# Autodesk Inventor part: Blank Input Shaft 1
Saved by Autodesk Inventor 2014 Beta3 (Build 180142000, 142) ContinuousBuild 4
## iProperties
Created: 2011-01
Part Number: Blank Input Shaft 1
Material: Steel
Document SubType Name: Modeling
Designer: Beta-8540w
Density: 1 g/cm^3
Appearance: Steel
CustomPartVersion: 1
Author: Beta-8540w
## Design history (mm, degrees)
sketch "Main Sketch"
  geometry: L1 (0, 0)-(43, 0) reference; L2 (0, 0)-(0, 45); L3 (12, 45)-(12, 6); L4 (0, 45)-(12, 45); L5 (15, 6)-(15, 5); L6 (12, 6)-(15, 6); L7 (43, 5)-(43, 0); L8 (15, 5)-(43, 5)
  constraints: 16 end point, 5 horizontal, 4 vertical
  dimensions: "d3" = 90 diameter of L4 L1 (derived); "d4" = 12 diameter of L6 L1 (derived); "d5" = 10 diameter of L8 L1 (derived)
revolve "Revolution1" sketch "Main Sketch" stored, may be unused: angle "d6" = 0 deg
chamfer "Chamfer1" distance "d7" = 0.5; stored, may be unused: second distance "d8" = 0.125, angle "d9" = 45 deg
node "Retaining Ring Groove1"
body "Solid1"
feature "iFeature27:1"
other parameters: "d0" = 0, "d1" = 0, "d2" = 0
